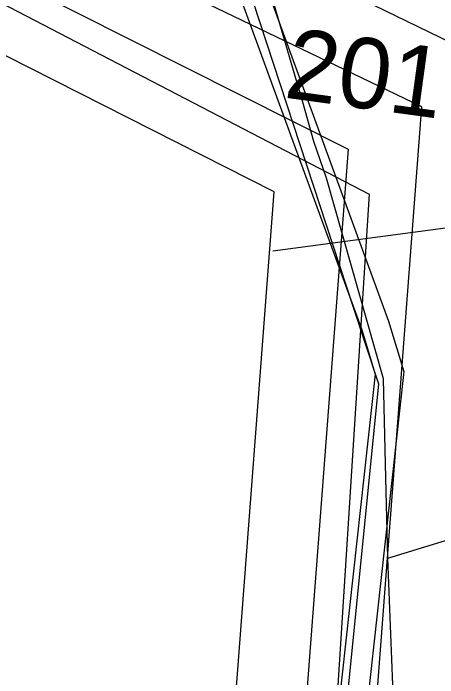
# Model space of a CAD drawing. Extents: x -746464 to -745690, y -1051581 to -1049993.
# Drawn here: x -746401.44 to -746395.4, y -1051044.13 to -1051034.69 of the extents above; entities that cross this region are included whole.
import ezdxf

# ---------------------------------------------------------------- set-up
doc = ezdxf.new("R2010")
doc.units = 0
for name, color, linetype in [('04_CETIN_NN', 7, 'Continuous'), ('04_CETIN_sdelovaci_podzem', 7, 'Continuous'), ('51_PVaK_kanal_popisy', 7, 'Continuous'), ('55_PREdi_NN', 7, 'Continuous'), ('55_PREdi_NN_popisy', 7, 'Continuous'), ('55_PREdi_VN', 7, 'Continuous')]:
    doc.layers.add(name, color=color, linetype=linetype)

msp = doc.modelspace()

# ---------------------------------------------------------------- linework, layer by layer
at = {"layer": '04_CETIN_NN'}
for points in [[(-746397.45, -1051035.5), (-746398, -1051033.62), (-746398.34, -1051032.11), (-746401.2, -1051030.47)], [(-746397.32, -1051035.95), (-746397.45, -1051035.5)], [(-746397.16, -1051036.51), (-746397.32, -1051035.95)], [(-746396.98, -1051037.03), (-746397.16, -1051036.51)], [(-746396.14, -1051041.29), (-746396.17, -1051039.88), (-746396.98, -1051037.03)], [(-746396.11, -1051042.43), (-746396.14, -1051041.29)], [(-746396.49, -1051052.67), (-746396.21, -1051050.24), (-746396.04, -1051044.23), (-746396.11, -1051042.43)]]:
    msp.add_lwpolyline(points, dxfattribs=at)
at = {"layer": '04_CETIN_sdelovaci_podzem'}
for points in [[(-746397.45, -1051035.5), (-746398, -1051033.62), (-746398.34, -1051032.11), (-746401.2, -1051030.47)], [(-746397.32, -1051035.95), (-746397.45, -1051035.5)], [(-746397.16, -1051036.51), (-746397.32, -1051035.95)], [(-746396.98, -1051037.03), (-746397.16, -1051036.51)], [(-746396.14, -1051041.29), (-746396.17, -1051039.88), (-746396.98, -1051037.03)], [(-746396.11, -1051042.43), (-746385.91, -1051039.31)], [(-746396.11, -1051042.43), (-746385.91, -1051039.31), (-746375.63, -1051039.64)], [(-746396.11, -1051042.43), (-746396.14, -1051041.29)], [(-746396.49, -1051052.67), (-746396.21, -1051050.24), (-746396.04, -1051044.23), (-746396.11, -1051042.43)]]:
    msp.add_lwpolyline(points, dxfattribs=at)
at = {"layer": '55_PREdi_NN'}
for points in [[(-746397.336, -1051057.726), (-746397.144, -1051055.927), (-746395.628, -1051036.016), (-746405.484, -1051031.281), (-746401.669, -1051020.053), (-746391.686, -1051022.407), (-746390.646, -1051017.325)], [(-746340.582, -1051017.778), (-746351.673, -1051021.52), (-746367.763, -1051024.007), (-746373.65, -1051024.219), (-746390.461, -1051022.407), (-746390.697, -1051023.631), (-746401.057, -1051021.324), (-746404.212, -1051030.74), (-746394.58, -1051035.412), (-746396.15, -1051056.033), (-746396.33, -1051057.725)], [(-746458.1072, -1051047.7978), (-746457.998, -1051047.783), (-746456.885, -1051048.928), (-746452.722, -1051047.69), (-746440.383, -1051033.636), (-746414.148, -1051029.846), (-746410.616, -1051029.61), (-746396.676, -1051036.62), (-746398.139, -1051055.821), (-746398.332, -1051057.639)], [(-746399.333, -1051057.595), (-746399.133, -1051055.715), (-746397.724, -1051037.224), (-746410.899, -1051030.552), (-746414.525, -1051030.787), (-746438.583, -1051034.365), (-746438.471, -1051035.121)], [(-746405.306, -1051032.615), (-746396.377, -1051037.258), (-746396.997, -1051046.987), (-746397.93, -1051056.94)]]:
    msp.add_lwpolyline(points, dxfattribs=at)
at = {"layer": '55_PREdi_NN_popisy'}
msp.add_lwpolyline([(-746397.746, -1051038.064), (-746389.881, -1051037.018), (-746380.967, -1051037.638)], dxfattribs=at)
at = {"layer": '55_PREdi_VN'}
for points in [[(-746458.1072, -1051037.3082), (-746457.572, -1051041.738), (-746446.525, -1051040.868), (-746440.303, -1051034.503), (-746440.014, -1051034.234), (-746413.813, -1051030.168), (-746402.109, -1051030.075), (-746399.106, -1051032.047), (-746398.436, -1051032.674), (-746396.101, -1051039.06), (-746395.882, -1051039.778), (-746397.231, -1051051.998)], [(-746458.1072, -1051040.7354), (-746458.016, -1051041.677), (-746446.463, -1051041.049), (-746439.847, -1051034.323), (-746436.082, -1051033.651), (-746413.853, -1051030.29), (-746407.61, -1051030.433), (-746402.17, -1051030.334), (-746399.206, -1051032.224), (-746398.587, -1051032.805), (-746396.606, -1051038.847), (-746396.244, -1051039.951), (-746397.448, -1051051.991), (-746397.722, -1051054.73), (-746397.683, -1051055.515), (-746397.64, -1051056.85)], [(-746458.1072, -1051040.6423), (-746457.923, -1051042.167), (-746446.344, -1051041.255), (-746440.023, -1051034.789), (-746439.831, -1051034.61), (-746413.781, -1051030.568), (-746402.227, -1051030.476), (-746399.354, -1051032.362), (-746398.779, -1051032.901), (-746396.48, -1051039.187), (-746396.289, -1051039.816), (-746396.864, -1051045.025), (-746397.97, -1051054.644), (-746397.923, -1051055.434)]]:
    msp.add_lwpolyline(points, dxfattribs=at)

# ---------------------------------------------------------------- texts
at = {"layer": '51_PVaK_kanal_popisy'}
msp.add_text('201,44', height=1, rotation=352.2109, dxfattribs=at).set_placement((-746397.602, -1051035.883))

doc.saveas('drawing.dxf')
